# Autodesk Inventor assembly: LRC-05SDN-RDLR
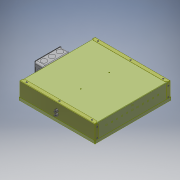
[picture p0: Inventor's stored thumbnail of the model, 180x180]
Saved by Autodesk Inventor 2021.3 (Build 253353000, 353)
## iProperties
Part Number: LRC-05SDN-RDLR
Document SubType Name: Assembly
Designer: JChurch
Author: JChurch
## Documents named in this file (5)
- X:\Revit Files\0000-Un-Zipped\COB\LRC-05SDN-RDL\LRC-05SDN-RDLR.iam
- X:\INVENTOR\830\830399-00-00.ipt
- X:\INVENTOR\885\885000-00-00.iam
- X:\INVENTOR\750\750905-XX-YY.iam
- X:\INVENTOR\KIRLIN_ENG\725\725075-02-00.ipt
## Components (4 placed, 4 different names)
1. 830399-00-00:1 — Mate:1, Mate:2, Mate:3, Mate:4, Mate:5, Angle:1, Insert:2
2. 885000-00-00:1 [sub-assembly] — Mate:4, Mate:5, Angle:1
3. 750905-XX-YY:1 [sub-assembly] — Insert:1, Insert:2
4. 725075-02-00:1 — Insert:1
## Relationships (8: Mate 5, Insert 2, Angle 1)
- Mate:1: 830399-00-00:1
- Mate:2: 830399-00-00:1
- Mate:3: 830399-00-00:1
- Mate:4: 830399-00-00:1 ↔ 885000-00-00:1
- Mate:5: 830399-00-00:1 ↔ 885000-00-00:1
- Angle:1: 830399-00-00:1 ↔ 885000-00-00:1
- Insert:1: 750905-XX-YY:1 ↔ 725075-02-00:1
- Insert:2: 830399-00-00:1 ↔ 750905-XX-YY:1
